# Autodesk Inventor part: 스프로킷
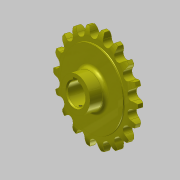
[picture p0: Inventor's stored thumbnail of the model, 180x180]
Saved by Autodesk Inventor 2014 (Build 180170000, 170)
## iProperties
Created: 2016-03
Part Number: 스프로킷
Material: 강철, 탄소
Document SubType Name: Modeling
Designer: mduedu
Density: 7.87 g/cm^3
Mass: 300.023 g
Surface Area: 127.848 cm^2
Volume: 38.1224 cm^3
Appearance: Yellow
Author: mduedu
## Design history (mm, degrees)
sketch "스케치1"
  geometry: L1 (0, 5)-(29.5, 5); L2 (29.5, 5)-(29.5, 4.1); L3 (30, 3.6)-(33.625, 3.6); L4 (40, 2)-(40, 0); L5 (40, 0)-(0, 0); L6 (0, 0)-(0, 5); L7 (0, -5)-(29.5, -5); L8 (29.5, -5)-(29.5, -4.1); L9 (30, -3.6)-(33.625, -3.6); L10 (40, -2)-(40, 0); L11 (0, 0)-(0, -5); A1 r 13.5 centre (33.625, -9.9) between (40, 2) and (33.625, 3.6); A2 r 13.5 centre (33.625, 9.9) between (33.625, -3.6) and (40, -2); A3 r 0.5 centre (30, 4.1) between (29.5, 4.1) and (30, 3.6); A4 r 0.5 centre (30, -4.1) between (30, -3.6) and (29.5, -4.1); 2 further points
  constraints: 22 end point, 8 point on circle, 6 symmetric about line, 5 tangent, 4 centre point, 4 parallel, 4 point on line, 1 equal radius, 1 horizontal, 1 perpendicular, 1 other
  dimensions: "d0" = 80 diameter of L4 L6; "d2" = 59 diameter of L2 L6; "d3" = 1.6 vertical distance of L4.start L3.end; "d4" = 3.6 distance from line of L4.end L3; "d5" = 5 distance between parallel lines of L5 L1; "d6" = 13.5 radius of A1; "d15" = 0.5 radius of A3
revolve "회전1" sketch "스케치1" stored, may be unused: angle "d7" = 90 deg
sketch "스케치2" dims "d8" = 65.2, "d11" = 80
  geometry: L1 (0, 0)-(0, 32.6); A1 r 36.57 centre (0, 0) between (-16.231, 32.771) and (0, 36.57); A2 r 3.97 centre (0, 36.57) between (-3.866, 35.665) and (0, 32.6); A3 r 12.7 centre (-16.231, 32.771) between (-3.866, 35.665) and (-5.534, 39.615); A4 r 12.7 centre (16.231, 32.771) between (5.534, 39.615) and (3.866, 35.665); A5 r 3.97 centre (0, 36.57) between (0, 32.6) and (3.866, 35.665); A6 r 40 centre (0, 0) between (5.534, 39.615) and (-5.534, 39.615); 2 further points
  constraints: 12 point on circle, 6 centre point, 4 coincident, 3 symmetric about line, 2 end point, 1 point on line, 1 tangent, 1 vertical, 1 vertical alignment, 7 other
  dimensions: "d10" = 73.14 diameter of A1; "d12" = 12.7 radius of A3
extrude "돌출1" cut sketch "스케치2" stored distance "d13" = 10; taper "d14" = 0 deg
sketch "스케치3"
  geometry: C1 r 13.5 at (0, 0); 1 further point
  constraints: 1 centre point, 1 coincident
  dimensions: "d19" = 27 diameter of C1
extrude "돌출2" join sketch "스케치3" distance "d20" = 13; taper "d21" = 0 deg
fillet "모깎기1" dims "d22" = 3
sketch "스케치4"
  geometry: L1 (-2.5, 0)-(2.5, 0); L2 (2.5, 0)-(2.5, 10.8); L3 (2.5, 10.8)-(-2.5, 10.8); L4 (-2.5, 10.8)-(-2.5, 0); C1 r 8.5 at (0, 0); 2 further points
  constraints: 8 end point, 2 coincident, 2 parallel, 1 centre point, 1 horizontal, 1 midpoint, 1 perpendicular
  dimensions: "d23" = 17 diameter of C1; "d25" = 5 distance of L2.end L3.end; "d26" = 10.8 distance of L1.end L2.end
extrude "돌출3" cut sketch "스케치4" stored distance "d27" = 8; taper "d28" = 0 deg
chamfer "모따기1" distance "d29" = 1; stored, may be unused: second distance "d30" = 2, angle "d31" = 45 deg
node "작업 평면1"
sketch "스케치5"
  geometry: L1 (13.5, 13)-(-13.5, 13) reference; 2 further points
  constraints: 1 vertical alignment
  dimensions: "d32" = 4 distance from line of point (0, 9) L1
hole "구멍1" sketch "스케치5" at (0, 9) diameter "d33" = 2.459; stored, may be unused: countersink angle "d37" = 90 deg, drill point angle "d39" = 118 deg; dims "d34" = 6, "d35" = 4, "d36" = 2, "d38" = 8
node "솔리드1"
pattern_circular "원형 패턴1" dims angle "d17" = 360 deg
